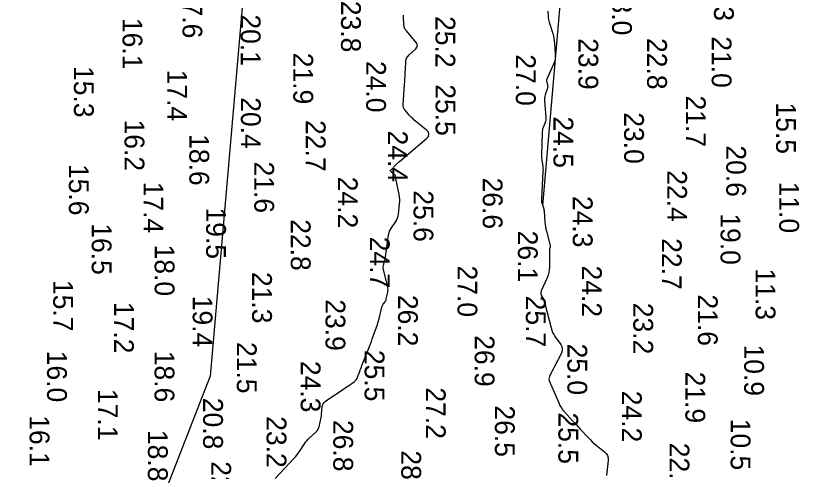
# Model space of a CAD drawing. Extents: x 1178573 to 1187098, y 693282 to 751751.
# Drawn here: x 1181951.5 to 1182446.5, y 722549.3 to 722836.9 of the extents above; entities that cross this region are included whole.
import ezdxf

# ---------------------------------------------------------------- set-up
doc = ezdxf.new("R2010")
doc.units = 0
for name, color, linetype in [('G-ANNO-PATT', 7, 'Continuous'), ('V-HYDS-MAJR', 7, 'Continuous'), ('V-HYDS-SOUN', 7, 'Continuous')]:
    doc.layers.add(name, color=color, linetype=linetype)

msp = doc.modelspace()

# ---------------------------------------------------------------- linework, layer by layer
at = {"layer": 'G-ANNO-PATT'}
msp.add_line((1182284.41, 722717.14), (1182404.98, 724104.25), dxfattribs=at)
for points in [[(1182192.54, 723969.84), (1182074.29, 722609.41), (1181796.18, 721896.63), (1181517.07, 721534.37), (1180724.06, 720916.39)], [(1182287.61, 722839.78), (1182287.84, 722836.25), (1182287.92, 722835.38), (1182288.06, 722834.51), (1182288.24, 722833.65), (1182288.48, 722832.8), (1182290.71, 722825.59), (1182291.12, 722824.1), (1182291.45, 722822.59), (1182291.69, 722821.07), (1182291.85, 722819.53), (1182292.34, 722812.64), (1182292.36, 722811), (1182292.18, 722809.38), (1182291.8, 722807.81), (1182291.22, 722806.27), (1182287.03, 722796.96), (1182286.87, 722796.5), (1182286.79, 722796.04), (1182286.8, 722795.56), (1182286.89, 722795.09), (1182287.42, 722793.16), (1182287.52, 722792.68), (1182287.54, 722792.2), (1182287.5, 722791.72), (1182287.38, 722791.24), (1182286, 722786.93), (1182285.77, 722786.04), (1182285.62, 722785.15), (1182285.55, 722784.25), (1182285.58, 722783.33), (1182286.37, 722772.67), (1182286.39, 722771.83), (1182286.31, 722771.01), (1182286.14, 722770.21), (1182285.88, 722769.42), (1182284.64, 722766.28), (1182284.36, 722765.49), (1182284.16, 722764.68), (1182284.03, 722763.86), (1182283.98, 722763.03), (1182283.64, 722748.85), (1182283.64, 722747.99), (1182283.67, 722747.13), (1182283.75, 722746.28), (1182283.86, 722745.43), (1182284.4, 722742.03), (1182284.51, 722741.18), (1182284.57, 722740.33), (1182284.59, 722739.47), (1182284.56, 722738.62), (1182283.54, 722721.24), (1182283.53, 722720.59), (1182283.59, 722719.95), (1182283.71, 722719.31), (1182283.89, 722718.68), (1182284.41, 722717.14)], [(1182115.47, 722544.78), (1182127.27, 722557.46), (1182128.19, 722558.49), (1182129.07, 722559.56), (1182129.9, 722560.66), (1182130.69, 722561.79), (1182133.92, 722566.65), (1182134.64, 722567.66), (1182135.42, 722568.62), (1182136.25, 722569.53), (1182137.14, 722570.39), (1182141.16, 722574.04), (1182141.85, 722574.76), (1182142.4, 722575.56), (1182142.84, 722576.43), (1182143.14, 722577.37), (1182144.1, 722581.31), (1182144.32, 722582.3), (1182144.5, 722583.29), (1182144.64, 722584.29), (1182144.75, 722585.3), (1182145.16, 722589.98), (1182145.36, 722591.03), (1182145.76, 722591.97), (1182146.38, 722592.78), (1182147.2, 722593.47), (1182158.23, 722600.99), (1182159.08, 722601.58), (1182159.95, 722602.16), (1182160.81, 722602.74), (1182161.67, 722603.32), (1182165.21, 722605.7), (1182165.97, 722606.3), (1182166.6, 722606.99), (1182167.11, 722607.78), (1182167.5, 722608.67), (1182168.81, 722612.39), (1182169.14, 722613.32), (1182169.48, 722614.24), (1182169.83, 722615.16), (1182170.19, 722616.08), (1182174.93, 722628.07), (1182175.55, 722629.68), (1182176.16, 722631.29), (1182176.76, 722632.91), (1182177.34, 722634.53), (1182179.95, 722641.95), (1182180.34, 722643.12), (1182180.71, 722644.3), (1182181.03, 722645.49), (1182181.33, 722646.68), (1182182.79, 722652.93), (1182182.93, 722653.41), (1182183.11, 722653.86), (1182183.34, 722654.29), (1182183.61, 722654.7), (1182184.79, 722656.31), (1182185.06, 722656.72), (1182185.29, 722657.15), (1182185.46, 722657.61), (1182185.6, 722658.08), (1182186.53, 722662.29), (1182186.66, 722663.15), (1182186.7, 722664.01), (1182186.64, 722664.87), (1182186.47, 722665.72), (1182183.75, 722676.38), (1182183.62, 722677.08), (1182183.58, 722677.77), (1182183.62, 722678.46), (1182183.76, 722679.16), (1182184.47, 722681.93), (1182184.64, 722682.63), (1182184.79, 722683.32), (1182184.92, 722684.03), (1182185.03, 722684.73), (1182187.07, 722698.59), (1182187.31, 722699.77), (1182187.68, 722700.91), (1182188.18, 722702), (1182188.8, 722703.04), (1182191.55, 722707.09), (1182192.17, 722708.13), (1182192.65, 722709.22), (1182192.99, 722710.36), (1182193.2, 722711.56), (1182193.94, 722718.05), (1182194.05, 722719.53), (1182194.05, 722721.02), (1182193.93, 722722.49), (1182193.7, 722723.96), (1182191.48, 722735.24), (1182191.33, 722735.74), (1182191.11, 722736.2), (1182190.8, 722736.6), (1182190.41, 722736.95), (1182188.7, 722738.26), (1182188.37, 722738.59), (1182188.24, 722738.94), (1182188.31, 722739.31), (1182188.59, 722739.69), (1182191.38, 722742.59), (1182191.98, 722743.19), (1182192.6, 722743.78), (1182193.22, 722744.35), (1182193.87, 722744.91), (1182211, 722759.38), (1182212.18, 722760.71), (1182212.56, 722762.04), (1182212.16, 722763.36), (1182210.97, 722764.67), (1182203.01, 722771.27), (1182202.25, 722771.93), (1182201.51, 722772.63), (1182200.8, 722773.36), (1182200.12, 722774.11), (1182197.48, 722777.2), (1182196.91, 722778), (1182196.52, 722778.87), (1182196.31, 722779.79), (1182196.29, 722780.78), (1182197.14, 722793.51), (1182197.25, 722795.19), (1182197.34, 722796.87), (1182197.43, 722798.54), (1182197.51, 722800.22), (1182197.84, 722807.48), (1182198.02, 722808.83), (1182198.45, 722810.07), (1182199.12, 722811.2), (1182200.03, 722812.21), (1182204.16, 722816.03), (1182204.95, 722817.01), (1182205.25, 722818.01), (1182205.07, 722819.03), (1182204.4, 722820.09), (1182198.27, 722827.31), (1182197.6, 722828.24), (1182197.12, 722829.23), (1182196.8, 722830.29), (1182196.67, 722831.42), (1182196.48, 722836.18), (1182196.45, 722837.29)]]:
    msp.add_lwpolyline(points, dxfattribs=at)
at = {"layer": 'V-HYDS-MAJR'}
for points in [[(1182287.61, 722839.78), (1182287.84, 722836.25), (1182287.92, 722835.38), (1182288.06, 722834.51), (1182288.24, 722833.65), (1182288.48, 722832.8), (1182290.71, 722825.59), (1182291.12, 722824.1), (1182291.45, 722822.59), (1182291.69, 722821.07), (1182291.85, 722819.53), (1182292.34, 722812.64), (1182292.36, 722811), (1182292.18, 722809.38), (1182291.8, 722807.81), (1182291.22, 722806.27), (1182287.03, 722796.96), (1182286.87, 722796.5), (1182286.79, 722796.04), (1182286.8, 722795.56), (1182286.89, 722795.09), (1182287.42, 722793.16), (1182287.52, 722792.68), (1182287.54, 722792.2), (1182287.5, 722791.72), (1182287.38, 722791.24), (1182286, 722786.93), (1182285.77, 722786.04), (1182285.62, 722785.15), (1182285.55, 722784.25), (1182285.58, 722783.33), (1182286.37, 722772.67), (1182286.39, 722771.83), (1182286.31, 722771.01), (1182286.14, 722770.21), (1182285.88, 722769.42), (1182284.64, 722766.28), (1182284.36, 722765.49), (1182284.16, 722764.68), (1182284.03, 722763.86), (1182283.98, 722763.03), (1182283.64, 722748.85), (1182283.64, 722747.99), (1182283.67, 722747.13), (1182283.75, 722746.28), (1182283.86, 722745.43), (1182284.4, 722742.03), (1182284.51, 722741.18), (1182284.57, 722740.33), (1182284.59, 722739.47), (1182284.56, 722738.62), (1182283.54, 722721.24), (1182283.53, 722720.59), (1182283.59, 722719.95), (1182283.71, 722719.31), (1182283.89, 722718.68), (1182284.73, 722716.19), (1182284.92, 722715.56), (1182285.08, 722714.92), (1182285.19, 722714.28), (1182285.26, 722713.63), (1182285.82, 722706.45), (1182285.96, 722705.03), (1182286.16, 722703.63), (1182286.42, 722702.24), (1182286.74, 722700.86), (1182289.01, 722691.93), (1182289.07, 722691.62), (1182289.09, 722691.32), (1182289.08, 722691.01), (1182289.03, 722690.7), (1182288.76, 722689.47), (1182288.7, 722689.17), (1182288.66, 722688.86), (1182288.64, 722688.54), (1182288.63, 722688.23), (1182288.64, 722678.27), (1182288.55, 722676.53), (1182288.28, 722674.82), (1182287.83, 722673.16), (1182287.19, 722671.53), (1182283.42, 722663.13), (1182283.2, 722662.48), (1182283.14, 722661.82), (1182283.24, 722661.17), (1182283.49, 722660.52), (1182284.82, 722657.95), (1182285.13, 722657.3), (1182285.41, 722656.63), (1182285.64, 722655.95), (1182285.83, 722655.25), (1182289.64, 722639.78), (1182290.07, 722638.31), (1182290.64, 722636.9), (1182291.34, 722635.55), (1182292.18, 722634.27), (1182295.78, 722629.24), (1182296.48, 722627.97), (1182296.78, 722626.67), (1182296.68, 722625.34), (1182296.18, 722623.97), (1182291.81, 722615.44), (1182291.41, 722614.65), (1182291.02, 722613.86), (1182290.63, 722613.07), (1182290.24, 722612.27), (1182288.69, 722609.09), (1182288.4, 722608.29), (1182288.29, 722607.49), (1182288.37, 722606.69), (1182288.63, 722605.88), (1182294.47, 722592.53), (1182295.26, 722590.91), (1182296.17, 722589.38), (1182297.2, 722587.92), (1182298.36, 722586.55), (1182303.24, 722581.22), (1182304.46, 722579.89), (1182305.68, 722578.56), (1182306.91, 722577.23), (1182308.14, 722575.91), (1182313.35, 722570.31), (1182314.5, 722569.11), (1182315.7, 722567.96), (1182316.93, 722566.85), (1182318.21, 722565.78), (1182323.39, 722561.6), (1182324.5, 722560.48), (1182325.25, 722559.2), (1182325.63, 722557.78), (1182325.64, 722556.2), (1182324.67, 722546.65)], [(1182115.47, 722544.78), (1182127.27, 722557.46), (1182128.19, 722558.49), (1182129.07, 722559.56), (1182129.9, 722560.66), (1182130.69, 722561.79), (1182133.92, 722566.65), (1182134.64, 722567.66), (1182135.42, 722568.62), (1182136.25, 722569.53), (1182137.14, 722570.39), (1182141.16, 722574.04), (1182141.85, 722574.76), (1182142.4, 722575.56), (1182142.84, 722576.43), (1182143.14, 722577.37), (1182144.1, 722581.31), (1182144.32, 722582.3), (1182144.5, 722583.29), (1182144.64, 722584.29), (1182144.75, 722585.3), (1182145.16, 722589.98), (1182145.36, 722591.03), (1182145.76, 722591.97), (1182146.38, 722592.78), (1182147.2, 722593.47), (1182158.23, 722600.99), (1182159.08, 722601.58), (1182159.95, 722602.16), (1182160.81, 722602.74), (1182161.67, 722603.32), (1182165.21, 722605.7), (1182165.97, 722606.3), (1182166.6, 722606.99), (1182167.11, 722607.78), (1182167.5, 722608.67), (1182168.81, 722612.39), (1182169.14, 722613.32), (1182169.48, 722614.24), (1182169.83, 722615.16), (1182170.19, 722616.08), (1182174.93, 722628.07), (1182175.55, 722629.68), (1182176.16, 722631.29), (1182176.76, 722632.91), (1182177.34, 722634.53), (1182179.95, 722641.95), (1182180.34, 722643.12), (1182180.71, 722644.3), (1182181.03, 722645.49), (1182181.33, 722646.68), (1182182.79, 722652.93), (1182182.93, 722653.41), (1182183.11, 722653.86), (1182183.34, 722654.29), (1182183.61, 722654.7), (1182184.79, 722656.31), (1182185.06, 722656.72), (1182185.29, 722657.15), (1182185.46, 722657.61), (1182185.6, 722658.08), (1182186.53, 722662.29), (1182186.66, 722663.15), (1182186.7, 722664.01), (1182186.64, 722664.87), (1182186.47, 722665.72), (1182183.75, 722676.38), (1182183.62, 722677.08), (1182183.58, 722677.77), (1182183.62, 722678.46), (1182183.76, 722679.16), (1182184.47, 722681.93), (1182184.64, 722682.63), (1182184.79, 722683.32), (1182184.92, 722684.03), (1182185.03, 722684.73), (1182187.07, 722698.59), (1182187.31, 722699.77), (1182187.68, 722700.91), (1182188.18, 722702), (1182188.8, 722703.04), (1182191.55, 722707.09), (1182192.17, 722708.13), (1182192.65, 722709.22), (1182192.99, 722710.36), (1182193.2, 722711.56), (1182193.94, 722718.05), (1182194.05, 722719.53), (1182194.05, 722721.02), (1182193.93, 722722.49), (1182193.7, 722723.96), (1182191.48, 722735.24), (1182191.33, 722735.74), (1182191.11, 722736.2), (1182190.8, 722736.6), (1182190.41, 722736.95), (1182188.7, 722738.26), (1182188.37, 722738.59), (1182188.24, 722738.94), (1182188.31, 722739.31), (1182188.59, 722739.69), (1182191.38, 722742.59), (1182191.98, 722743.19), (1182192.6, 722743.78), (1182193.22, 722744.35), (1182193.87, 722744.91), (1182211, 722759.38), (1182212.18, 722760.71), (1182212.56, 722762.04), (1182212.16, 722763.36), (1182210.97, 722764.67), (1182203.01, 722771.27), (1182202.25, 722771.93), (1182201.51, 722772.63), (1182200.8, 722773.36), (1182200.12, 722774.11), (1182197.48, 722777.2), (1182196.91, 722778), (1182196.52, 722778.87), (1182196.31, 722779.79), (1182196.29, 722780.78), (1182197.14, 722793.51), (1182197.25, 722795.19), (1182197.34, 722796.87), (1182197.43, 722798.54), (1182197.51, 722800.22), (1182197.84, 722807.48), (1182198.02, 722808.83), (1182198.45, 722810.07), (1182199.12, 722811.2), (1182200.03, 722812.21), (1182204.16, 722816.03), (1182204.95, 722817.01), (1182205.25, 722818.01), (1182205.07, 722819.03), (1182204.4, 722820.09), (1182198.27, 722827.31), (1182197.6, 722828.24), (1182197.12, 722829.23), (1182196.8, 722830.29), (1182196.67, 722831.42), (1182196.48, 722836.18), (1182196.45, 722837.29)]]:
    msp.add_lwpolyline(points, dxfattribs=at)

# ---------------------------------------------------------------- texts
at = {"layer": 'V-HYDS-SOUN'}
for s, p in [('21.3 ', (1182392.58, 722866.12)), ('17.6 ', (1182056.88, 722855.16)), ('23.0 ', (1182328.21, 722857.07)), ('23.8 ', (1182157.02, 722846.33)), ('16.1 ', (1182019.03, 722835.53)), ('20.1 ', (1182093.67, 722837.76)), ('25.2 ', (1182216.65, 722836.69)), ('21.0 ', (1182391.13, 722823.94)), ('23.9 ', (1182306.96, 722822.74)), ('22.8 ', (1182350.36, 722822.84)), ('21.9 ', (1182126.87, 722813.53)), ('27.0 ', (1182267.45, 722812.55)), ('15.3 ', (1181988.31, 722805.16)), ('24.0 ', (1182172.89, 722808.35)), ('17.4 ', (1182047.3, 722802.84)), ('25.5 ', (1182216.77, 722793.62)), ('20.4 ', (1182093.79, 722785.45)), ('21.7 ', (1182374.86, 722786.52)), ('15.5 ', (1182431.83, 722782.14)), ('23.0 ', (1182335.82, 722775.94)), ('16.2 ', (1182020.29, 722771.36)), ('22.7 ', (1182134.74, 722771.07)), ('24.5 ', (1182291.18, 722773.32)), ('24.4 ', (1182186.57, 722764.42)), ('18.6 ', (1182061.21, 722762.15)), ('20.6 ', (1182400.32, 722755.06)), ('21.6 ', (1182102.22, 722744.86)), ('15.6 ', (1181985.13, 722743.32)), ('24.2 ', (1182155, 722735.28)), ('26.6 ', (1182246.52, 722734.72)), ('22.4 ', (1182363.02, 722739.39)), ('17.4 ', (1182032.24, 722732.14)), ('11.0 ', (1182433.79, 722732.17)), ('25.6 ', (1182202.81, 722726.68)), ('24.3 ', (1182303.4, 722723.14)), ('19.5 ', (1182071.82, 722715.84)), ('19.0 ', (1182396.74, 722712.16)), ('16.5 ', (1181999.54, 722705.86)), ('22.8 ', (1182125.27, 722708.44)), ('26.1 ', (1182268.74, 722701.22)), ('24.7 ', (1182175.22, 722697.42)), ('22.7 ', (1182359.64, 722696.47)), ('18.0 ', (1182039.3, 722692.41)), ('27.0 ', (1182230.57, 722679.19)), ('24.2 ', (1182309.2, 722679.21)), ('11.3 ', (1182418.89, 722677.34)), ('21.3 ', (1182100.85, 722675.17)), ('15.7 ', (1181975.22, 722670.09)), ('26.2 ', (1182193.03, 722660.67)), ('21.6 ', (1182382.41, 722660.93)), ('17.2 ', (1182013.63, 722656.24)), ('19.4 ', (1182063.31, 722660.12)), ('23.9 ', (1182147.21, 722657.88)), ('25.7 ', (1182273.78, 722660.18)), ('23.2 ', (1182341.62, 722655.68)), ('21.5 ', (1182091.21, 722630.93)), ('26.9 ', (1182241.44, 722635.21)), ('25.5 ', (1182171.92, 722625.94)), ('25.0 ', (1182299.99, 722629.94)), ('10.9 ', (1182411.65, 722629.34)), ('16.0 ', (1181971.32, 722625.41)), ('18.6 ', (1182039.23, 722625.4)), ('24.3 ', (1182131.55, 722619.01)), ('21.9 ', (1182374.51, 722612.21)), ('27.2 ', (1182210.58, 722602.27)), ('17.1 ', (1182003.48, 722601.28)), ('24.2 ', (1182334.43, 722600.14)), ('20.8 ', (1182069.92, 722595.68)), ('26.5 ', (1182254.23, 722590.87)), ('25.5 ', (1182294.29, 722586.44)), ('16.1 ', (1181960.34, 722584.68)), ('23.2 ', (1182109.99, 722584.09)), ('26.8 ', (1182152.14, 722581.7)), ('10.5 ', (1182403.12, 722582.47)), ('18.8 ', (1182035.04, 722575.4)), ('22.2 ', (1182364.52, 722567.3)), ('28.7 ', (1182195.1, 722562.48)), ('22.5 ', (1182075.07, 722555.66))]:
    msp.add_text(s, height=12.5, rotation=270, dxfattribs=at).set_placement(p)

doc.saveas('drawing.dxf')
